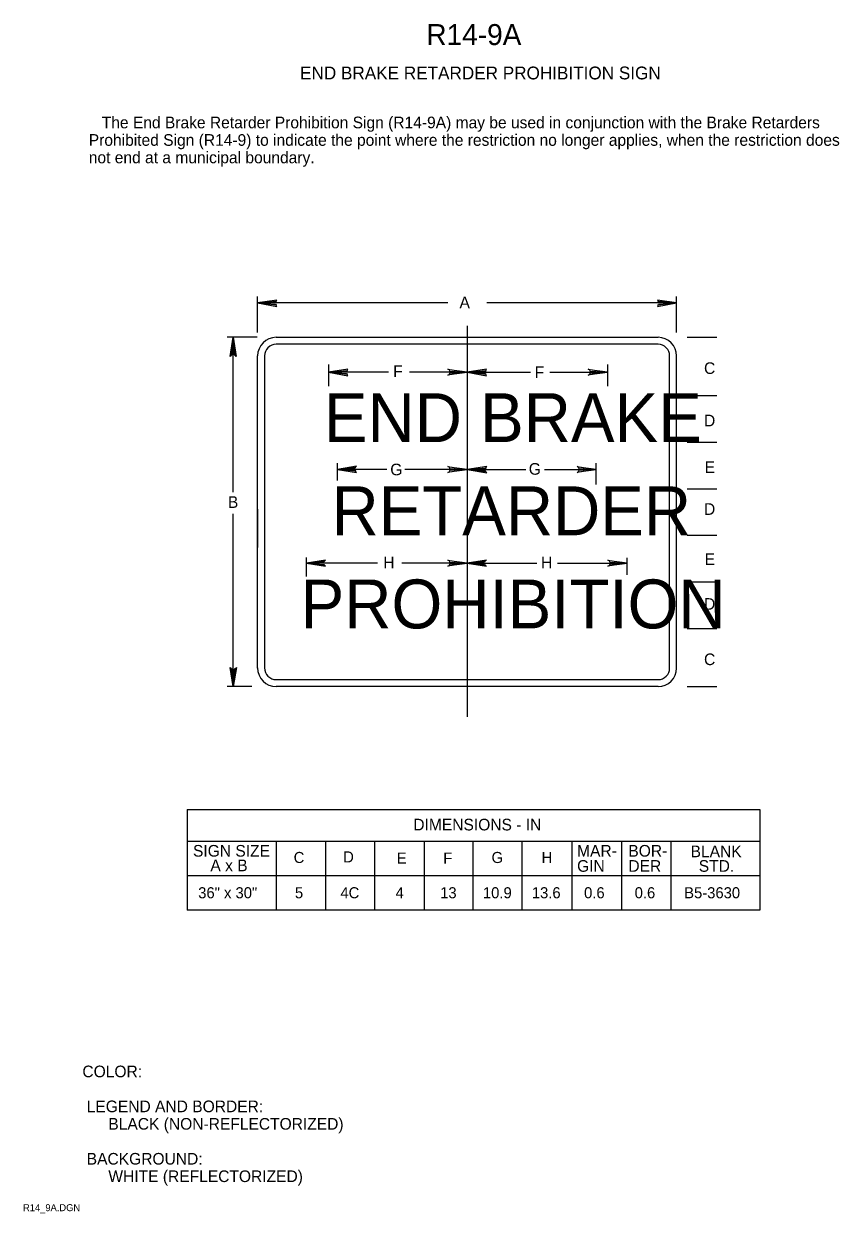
# Model space of a CAD drawing. Extents: x 0.013 to 0.188, y 0.004 to 0.259.
import ezdxf

# ---------------------------------------------------------------- set-up
doc = ezdxf.new("R2010")
doc.units = 0
doc.layers.add('1', color=7, linetype='Continuous')
doc.layers.add('12', color=7, linetype='Continuous')

msp = doc.modelspace()

# ---------------------------------------------------------------- linework, layer by layer
at = {"layer": '12'}
for p, q in [((0.06275, 0.193), (0.06275, 0.20075)), ((0.10363, 0.19937), (0.06275, 0.19937)), ((0.15275, 0.19937), (0.112, 0.19937)), ((0.15275, 0.193), (0.15275, 0.20075)), ((0.10775, 0.1945), (0.10775, 0.1105)), ((0.06263, 0.192), (0.05625, 0.192)), ((0.0575, 0.15875), (0.0575, 0.192)), ((0.06675, 0.192), (0.14875, 0.192)), ((0.155, 0.192), (0.16137, 0.192)), ((0.14875, 0.1905), (0.06675, 0.1905)), ((0.06275, 0.121), (0.06275, 0.188)), ((0.06425, 0.188), (0.06425, 0.121)), ((0.15125, 0.121), (0.15125, 0.188)), ((0.15275, 0.121), (0.15275, 0.188)), ((0.078, 0.18613), (0.078, 0.1815)), ((0.09087, 0.1845), (0.078, 0.1845)), ((0.10775, 0.1845), (0.09538, 0.1845)), ((0.10775, 0.1845), (0.12137, 0.1845)), ((0.1255, 0.1845), (0.13787, 0.1845)), ((0.13787, 0.18613), (0.13787, 0.1815)), ((0.155, 0.1795), (0.16137, 0.1795)), ((0.155, 0.1695), (0.16137, 0.1695)), ((0.07988, 0.16125), (0.07988, 0.165)), ((0.0905, 0.16362), (0.07988, 0.16362)), ((0.10775, 0.16362), (0.09438, 0.16362)), ((0.10775, 0.16362), (0.12037, 0.16362)), ((0.12437, 0.16362), (0.1355, 0.16362)), ((0.1355, 0.16037), (0.1355, 0.165)), ((0.155, 0.1595), (0.16137, 0.1595)), ((0.0575, 0.117), (0.0575, 0.15413)), ((0.06275, 0.15513), (0.06275, 0.14688)), ((0.155, 0.1495), (0.16137, 0.1495)), ((0.07325, 0.14062), (0.07325, 0.14475)), ((0.0885, 0.1435), (0.07325, 0.1435)), ((0.10775, 0.1435), (0.09375, 0.1435)), ((0.10775, 0.1435), (0.12275, 0.1435)), ((0.12713, 0.1435), (0.14213, 0.1435)), ((0.14213, 0.141), (0.14213, 0.14463)), ((0.155, 0.1395), (0.16137, 0.1395)), ((0.155, 0.1295), (0.16137, 0.1295)), ((0.06675, 0.1185), (0.14875, 0.1185)), ((0.0615, 0.117), (0.05625, 0.117)), ((0.14875, 0.117), (0.06675, 0.117)), ((0.155, 0.117), (0.16137, 0.117)), ((0.04763, 0.09062), (0.17062, 0.09062)), ((0.04763, 0.09062), (0.04763, 0.069)), ((0.17062, 0.09062), (0.17062, 0.069)), ((0.17062, 0.08375), (0.04763, 0.08375)), ((0.06675, 0.08375), (0.06675, 0.069)), ((0.07737, 0.08375), (0.07737, 0.069)), ((0.08788, 0.08375), (0.08788, 0.069)), ((0.0985, 0.08375), (0.0985, 0.069)), ((0.109, 0.08375), (0.109, 0.069)), ((0.1195, 0.08375), (0.1195, 0.069)), ((0.13025, 0.08375), (0.13025, 0.069)), ((0.14088, 0.08375), (0.14088, 0.069)), ((0.1515, 0.08375), (0.1515, 0.069)), ((0.17062, 0.07637), (0.04763, 0.07637)), ((0.17062, 0.069), (0.04763, 0.069))]:
    msp.add_line(p, q, dxfattribs=at)
for points in [[(0.06675, 0.19975), (0.06663, 0.1995), (0.06275, 0.19937), (0.06675, 0.19975), (0.06688, 0.2), (0.06275, 0.19937), (0.06663, 0.19912), (0.06675, 0.19887), (0.06275, 0.19937), (0.06688, 0.19862), (0.06675, 0.19887)], [(0.14875, 0.19887), (0.14888, 0.19912), (0.15275, 0.19937), (0.14875, 0.19887), (0.14863, 0.19862), (0.15275, 0.19937), (0.14888, 0.1995), (0.14875, 0.19975), (0.15275, 0.19937), (0.14863, 0.2), (0.14875, 0.19975)], [(0.057, 0.18813), (0.05725, 0.18825), (0.0575, 0.192), (0.057, 0.18813), (0.05688, 0.18788), (0.0575, 0.192), (0.05775, 0.18825), (0.058, 0.18813), (0.0575, 0.192), (0.05813, 0.18788), (0.058, 0.18813)], [(0.082, 0.18488), (0.08188, 0.18463), (0.078, 0.1845), (0.082, 0.18488), (0.08213, 0.18513), (0.078, 0.1845), (0.08188, 0.18425), (0.082, 0.184), (0.078, 0.1845), (0.08213, 0.18375), (0.082, 0.184)], [(0.10388, 0.185), (0.104, 0.18475), (0.10775, 0.1845), (0.10388, 0.185), (0.10363, 0.18513), (0.10775, 0.1845), (0.104, 0.18425), (0.10388, 0.184), (0.10775, 0.1845), (0.10363, 0.18388), (0.10388, 0.184)], [(0.11175, 0.18488), (0.11163, 0.18463), (0.10775, 0.1845), (0.11175, 0.18488), (0.11188, 0.18513), (0.10775, 0.1845), (0.11163, 0.18425), (0.11175, 0.184), (0.10775, 0.1845), (0.11188, 0.18375), (0.11175, 0.184)], [(0.134, 0.185), (0.13412, 0.18475), (0.13787, 0.1845), (0.134, 0.185), (0.13375, 0.18513), (0.13787, 0.1845), (0.13412, 0.18425), (0.134, 0.184), (0.13787, 0.1845), (0.13375, 0.18388), (0.134, 0.184)], [(0.08375, 0.16412), (0.08363, 0.16387), (0.07988, 0.16362), (0.08375, 0.16412), (0.084, 0.16437), (0.07988, 0.16362), (0.08363, 0.1635), (0.08375, 0.16325), (0.07988, 0.16362), (0.084, 0.163), (0.08375, 0.16325)], [(0.10388, 0.16412), (0.104, 0.16387), (0.10775, 0.16362), (0.10388, 0.16412), (0.10363, 0.16425), (0.10775, 0.16362), (0.104, 0.16337), (0.10388, 0.16312), (0.10775, 0.16362), (0.10363, 0.163), (0.10388, 0.16312)], [(0.11175, 0.164), (0.11163, 0.16375), (0.10775, 0.16362), (0.11175, 0.164), (0.112, 0.16425), (0.10775, 0.16362), (0.11163, 0.16337), (0.11175, 0.16312), (0.10775, 0.16362), (0.112, 0.16287), (0.11175, 0.16312)], [(0.13162, 0.16412), (0.13175, 0.16387), (0.1355, 0.16362), (0.13162, 0.16412), (0.13137, 0.16425), (0.1355, 0.16362), (0.13175, 0.16337), (0.13162, 0.16312), (0.1355, 0.16362), (0.13137, 0.163), (0.13162, 0.16312)], [(0.07712, 0.144), (0.077, 0.14375), (0.07325, 0.1435), (0.07712, 0.144), (0.07737, 0.14413), (0.07325, 0.1435), (0.077, 0.14325), (0.07712, 0.143), (0.07325, 0.1435), (0.07737, 0.14288), (0.07712, 0.143)], [(0.10388, 0.144), (0.104, 0.14375), (0.10775, 0.1435), (0.10388, 0.144), (0.10363, 0.14413), (0.10775, 0.1435), (0.104, 0.14325), (0.10388, 0.143), (0.10775, 0.1435), (0.10363, 0.14288), (0.10388, 0.143)], [(0.11163, 0.144), (0.1115, 0.14375), (0.10775, 0.1435), (0.11163, 0.144), (0.11188, 0.14413), (0.10775, 0.1435), (0.1115, 0.14325), (0.11163, 0.143), (0.10775, 0.1435), (0.11188, 0.14288), (0.11163, 0.143)], [(0.13825, 0.144), (0.13837, 0.14375), (0.14213, 0.1435), (0.13825, 0.144), (0.138, 0.14413), (0.14213, 0.1435), (0.13837, 0.14325), (0.13825, 0.143), (0.14213, 0.1435), (0.138, 0.14288), (0.13825, 0.143)], [(0.058, 0.12087), (0.05775, 0.12075), (0.0575, 0.117), (0.058, 0.12087), (0.05825, 0.12112), (0.0575, 0.117), (0.05738, 0.12075), (0.057, 0.12087), (0.0575, 0.117), (0.05688, 0.12112), (0.057, 0.12087)]]:
    msp.add_lwpolyline(points, dxfattribs=at)
for centre, radius, start, end in [((0.06675, 0.188), 0.004, 90, 180), ((0.14875, 0.188), 0.004, 0, 90), ((0.06675, 0.188), 0.0025, 90, 180), ((0.14875, 0.188), 0.0025, 0, 90), ((0.06677, 0.12101), 0.00401, 179.7743, 269.7743), ((0.06677, 0.12101), 0.00251, 179.6396, 269.6396), ((0.14875, 0.121), 0.004, 270, 0), ((0.14875, 0.121), 0.0025, 270, 0)]:
    msp.add_arc(centre, radius, start, end, dxfattribs=at)

# ---------------------------------------------------------------- texts
at = {"layer": '1'}
for s, height, p in [('R14-9A', 0.0045, (0.099, 0.25475)), ('END BRAKE RETARDER PROHIBITION SIGN', 0.0027503, (0.07188, 0.24738))]:
    msp.add_text(s, height=height, dxfattribs=at).set_placement(p)
at = {"layer": '12'}
for s, height, p in [('   The End Brake Retarder Prohibition Sign (R14-9A) may be used in conjunction with the Brake Retarders', 0.00249975, (0.0265, 0.23688)), ('Prohibited Sign (R14-9) to indicate the point where the restriction no longer applies, when the restriction does', 0.00249975, (0.0265, 0.23312)), ('not end at a municipal boundary.', 0.0024998, (0.0265, 0.22937)), ('A', 0.0025, (0.10612, 0.19825)), ('C', 0.0025, (0.15863, 0.18413)), ('F', 0.0025, (0.09187, 0.1835)), ('F', 0.0025, (0.12225, 0.18325)), ('END BRAKE', 0.0105, (0.077, 0.1695)), ('D', 0.0025, (0.15863, 0.17288)), ('G', 0.0025, (0.09125, 0.16237)), ('G', 0.0025, (0.121, 0.1625)), ('E', 0.0025, (0.15875, 0.16287)), ('RETARDER', 0.0105, (0.07863, 0.1495)), ('B', 0.0025, (0.05638, 0.15538)), ('D', 0.0025, (0.15863, 0.15388)), ('E', 0.0025, (0.15875, 0.14313)), ('H', 0.0025, (0.08975, 0.14238)), ('H', 0.0025, (0.12362, 0.14238)), ('PROHIBITION', 0.0105, (0.072, 0.1295)), ('D', 0.0025, (0.15863, 0.1335)), ('C', 0.0025, (0.15863, 0.12162)), ('DIMENSIONS - IN', 0.0024998, (0.0962, 0.08613)), ('SIGN SIZE', 0.0025, (0.04888, 0.0805)), ('MAR-', 0.0025, (0.13137, 0.0805)), ('BOR-', 0.0025, (0.14238, 0.0805)), ('BLANK', 0.0025, (0.15575, 0.08038)), ('A x B', 0.0025, (0.05262, 0.07737)), ('C', 0.00238, (0.0705, 0.07913)), ('D', 0.00238, (0.08113, 0.07925)), ('E', 0.00238, (0.09262, 0.079)), ('F', 0.00238, (0.10263, 0.079)), ('G', 0.00238, (0.113, 0.07913)), ('H', 0.00238, (0.12375, 0.07913)), ('GIN', 0.0025, (0.13137, 0.07725)), ('DER', 0.0025, (0.14238, 0.07725)), ('STD.', 0.0025, (0.1575, 0.07725)), ('36" x 30"', 0.002375, (0.05, 0.07156)), ('5', 0.00238, (0.07077, 0.07156)), ('4C', 0.002375, (0.08054, 0.07156)), ('4', 0.00238, (0.09239, 0.07156)), ('13', 0.002375, (0.10196, 0.07156)), ('10.9', 0.002375, (0.11115, 0.07156)), ('13.6', 0.002375, (0.12165, 0.07156)), ('0.6', 0.002375, (0.13287, 0.07156)), ('0.6', 0.002375, (0.14374, 0.07156)), ('B5-3630', 0.002375, (0.15437, 0.07156)), ('COLOR:', 0.0025, (0.02513, 0.03313)), (' LEGEND AND BORDER:', 0.0024998, (0.02513, 0.02563)), ('      BLACK (NON-REFLECTORIZED)', 0.0024998, (0.02513, 0.02188)), (' BACKGROUND:', 0.0024998, (0.02513, 0.01438)), ('      WHITE (REFLECTORIZED)', 0.0024998, (0.02513, 0.01063)), ('R14_9A.DGN', 0.0015, (0.01238, 0.00438))]:
    msp.add_text(s, height=height, dxfattribs=at).set_placement(p)

doc.saveas('drawing.dxf')
